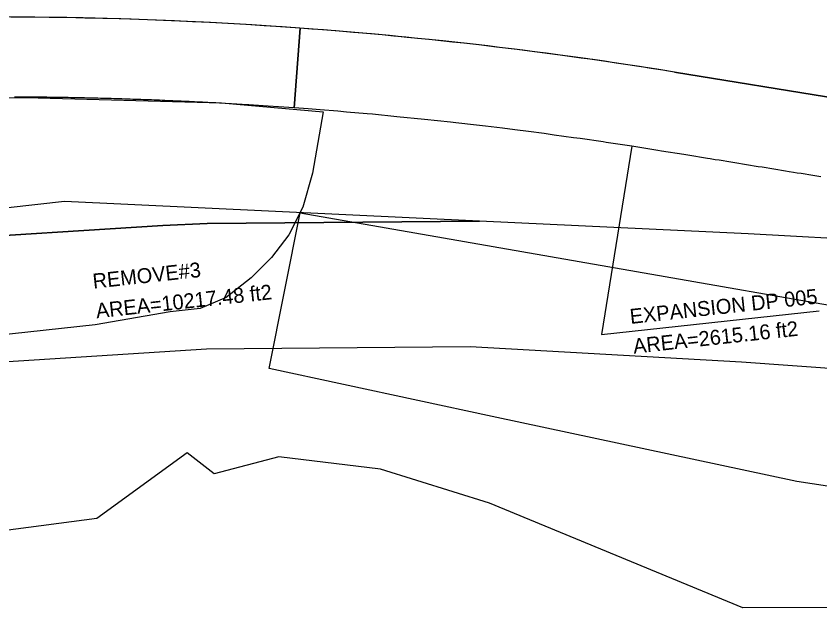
# Model space of a CAD drawing. Extents: x 1509538 to 1510847, y 401283 to 402022.
# Drawn here: x 1510184.5 to 1510335.3, y 401595.2 to 401706.3 of the extents above; entities that cross this region are included whole.
import ezdxf

# ---------------------------------------------------------------- set-up
doc = ezdxf.new("R2010")
doc.units = 0
for name, color, linetype in [('LAWE_P_T', 7, 'Continuous'), ('LDEFAULT_P', 7, 'Continuous'), ('Level 14', 7, 'Continuous'), ('Level 16', 7, 'Continuous'), ('Level 17', 7, 'Continuous'), ('Level 21', 7, 'Continuous'), ('Level 22', 7, 'Continuous'), ('Level 24', 7, 'Continuous'), ('Level 3', 7, 'Continuous'), ('Level 4', 7, 'Continuous')]:
    doc.layers.add(name, color=color, linetype=linetype)

msp = doc.modelspace()

# ---------------------------------------------------------------- linework, layer by layer
at = {"layer": 'LDEFAULT_P'}
msp.add_lwpolyline([(1510300.06, 401681.85), (1510294.35, 401646.54), (1510335.18, 401650.99)], dxfattribs=at)
at = {"layer": 'Level 14'}
msp.add_line((1510433.17, 401675.46), (1510308.05, 401695.77), dxfattribs=at)
msp.add_arc((1510179.87, 400906.1), 800, 80.78048, 96.2219, dxfattribs=at)
at = {"layer": 'Level 16'}
for p, q in [((1510184.72, 401691.09), (1510184.22, 401691.09)), ((1510185.23, 401691.08), (1510184.72, 401691.09)), ((1510185.73, 401691.08), (1510185.23, 401691.08)), ((1510186.24, 401691.08), (1510185.73, 401691.08)), ((1510186.74, 401691.07), (1510186.24, 401691.08)), ((1510187.25, 401691.07), (1510186.74, 401691.07)), ((1510187.75, 401691.06), (1510187.25, 401691.07)), ((1510188.25, 401691.06), (1510187.75, 401691.06)), ((1510188.76, 401691.05), (1510188.25, 401691.06)), ((1510189.26, 401691.04), (1510188.76, 401691.05)), ((1510189.77, 401691.04), (1510189.26, 401691.04)), ((1510190.27, 401691.03), (1510189.77, 401691.04)), ((1510190.77, 401691.02), (1510190.27, 401691.03)), ((1510191.28, 401691.02), (1510190.77, 401691.02)), ((1510191.78, 401691.01), (1510191.28, 401691.02)), ((1510192.29, 401691), (1510191.78, 401691.01)), ((1510192.79, 401690.99), (1510192.29, 401691)), ((1510193.3, 401690.99), (1510192.79, 401690.99)), ((1510193.8, 401690.98), (1510193.3, 401690.99)), ((1510194.3, 401690.97), (1510193.8, 401690.98)), ((1510194.81, 401690.96), (1510194.3, 401690.97)), ((1510195.31, 401690.95), (1510194.81, 401690.96)), ((1510195.82, 401690.94), (1510195.31, 401690.95)), ((1510196.32, 401690.93), (1510195.82, 401690.94)), ((1510196.82, 401690.92), (1510196.32, 401690.93)), ((1510197.33, 401690.91), (1510196.82, 401690.92)), ((1510197.83, 401690.9), (1510197.33, 401690.91)), ((1510198.34, 401690.88), (1510197.83, 401690.9)), ((1510198.84, 401690.87), (1510198.34, 401690.88)), ((1510199.34, 401690.86), (1510198.84, 401690.87)), ((1510199.85, 401690.85), (1510199.34, 401690.86)), ((1510200.35, 401690.83), (1510199.85, 401690.85)), ((1510200.86, 401690.82), (1510200.35, 401690.83)), ((1510201.36, 401690.81), (1510200.86, 401690.82)), ((1510201.86, 401690.79), (1510201.36, 401690.81)), ((1510202.37, 401690.78), (1510201.86, 401690.79)), ((1510202.87, 401690.76), (1510202.37, 401690.78)), ((1510203.38, 401690.75), (1510202.87, 401690.76)), ((1510203.88, 401690.73), (1510203.38, 401690.75)), ((1510204.38, 401690.72), (1510203.88, 401690.73)), ((1510204.89, 401690.7), (1510204.38, 401690.72)), ((1510205.39, 401690.69), (1510204.89, 401690.7)), ((1510205.9, 401690.67), (1510205.39, 401690.69)), ((1510206.4, 401690.65), (1510205.9, 401690.67)), ((1510206.9, 401690.64), (1510206.4, 401690.65)), ((1510207.41, 401690.62), (1510206.9, 401690.64)), ((1510207.91, 401690.6), (1510207.41, 401690.62)), ((1510208.42, 401690.58), (1510207.91, 401690.6)), ((1510208.92, 401690.56), (1510208.42, 401690.58)), ((1510209.42, 401690.54), (1510208.92, 401690.56)), ((1510209.93, 401690.53), (1510209.42, 401690.54)), ((1510210.43, 401690.51), (1510209.93, 401690.53)), ((1510210.93, 401690.49), (1510210.43, 401690.51)), ((1510211.44, 401690.47), (1510210.93, 401690.49)), ((1510211.94, 401690.45), (1510211.44, 401690.47)), ((1510212.45, 401690.42), (1510211.94, 401690.45)), ((1510212.95, 401690.4), (1510212.45, 401690.42)), ((1510213.45, 401690.38), (1510212.95, 401690.4)), ((1510213.96, 401690.36), (1510213.45, 401690.38)), ((1510214.46, 401690.34), (1510213.96, 401690.36)), ((1510214.96, 401690.32), (1510214.46, 401690.34)), ((1510215.47, 401690.29), (1510214.96, 401690.32)), ((1510215.97, 401690.27), (1510215.47, 401690.29)), ((1510216.48, 401690.25), (1510215.97, 401690.27)), ((1510216.98, 401690.22), (1510216.48, 401690.25)), ((1510217.48, 401690.2), (1510216.98, 401690.22)), ((1510217.99, 401690.17), (1510217.48, 401690.2)), ((1510218.49, 401690.15), (1510217.99, 401690.17)), ((1510218.99, 401690.13), (1510218.49, 401690.15)), ((1510219.5, 401690.1), (1510218.99, 401690.13)), ((1510220, 401690.08), (1510219.5, 401690.1)), ((1510220.5, 401690.05), (1510220, 401690.08)), ((1510221.01, 401690.02), (1510220.5, 401690.05)), ((1510221.51, 401690), (1510221.01, 401690.02)), ((1510222.02, 401689.97), (1510221.51, 401690)), ((1510222.66, 401689.93), (1510222.02, 401689.97)), ((1510224.95, 401689.81), (1510222.66, 401689.93)), ((1510226.91, 401689.69), (1510224.95, 401689.81)), ((1510228.21, 401689.61), (1510226.91, 401689.69)), ((1510231.81, 401689.38), (1510228.21, 401689.61)), ((1510233.77, 401689.25), (1510231.81, 401689.38)), ((1510236.7, 401689.04), (1510233.77, 401689.25))]:
    msp.add_line(p, q, dxfattribs=at)
msp.add_lwpolyline([(1510237.79, 401704), (1510236.7, 401689.04)], dxfattribs=at)
msp.add_arc((1510179.87, 400906.1), 800, 85.84827, 96.2219, dxfattribs=at)
at = {"layer": 'Level 17'}
for p, q in [((1510236.7, 401689.04), (1510237.79, 401704)), ((1510308.05, 401695.77), (1510410.94, 401679.07)), ((1510236.7, 401689.04), (1510236.7, 401689.04)), ((1510239.32, 401688.85), (1510236.7, 401689.04)), ((1510241.6, 401688.67), (1510239.32, 401688.85)), ((1510244.87, 401688.41), (1510241.6, 401688.67)), ((1510246.49, 401688.27), (1510244.87, 401688.41)), ((1510250.42, 401687.92), (1510246.49, 401688.27)), ((1510251.37, 401687.84), (1510250.42, 401687.92)), ((1510255.96, 401687.4), (1510251.37, 401687.84)), ((1510261.14, 401686.88), (1510255.96, 401687.4)), ((1510266.02, 401686.36), (1510261.14, 401686.88)), ((1510267.04, 401686.25), (1510266.02, 401686.36)), ((1510270.89, 401685.81), (1510267.04, 401686.25)), ((1510272.57, 401685.61), (1510270.89, 401685.81)), ((1510275.76, 401685.22), (1510272.57, 401685.61)), ((1510278.09, 401684.93), (1510275.76, 401685.22)), ((1510280.63, 401684.61), (1510278.09, 401684.93)), ((1510283.61, 401684.22), (1510280.63, 401684.61)), ((1510285.5, 401683.96), (1510283.61, 401684.22)), ((1510289.13, 401683.46), (1510285.5, 401683.96)), ((1510290.35, 401683.29), (1510289.13, 401683.46)), ((1510294.64, 401682.67), (1510290.35, 401683.29)), ((1510295.21, 401682.58), (1510294.64, 401682.67)), ((1510300.06, 401681.85), (1510295.21, 401682.58)), ((1510304.91, 401681.08), (1510300.06, 401681.85)), ((1510305.64, 401680.96), (1510304.91, 401681.08)), ((1510309.83, 401680.28), (1510305.64, 401680.96)), ((1510310.56, 401680.16), (1510309.83, 401680.28)), ((1510311.29, 401680.04), (1510310.56, 401680.16)), ((1510312.03, 401679.92), (1510311.29, 401680.04)), ((1510312.76, 401679.8), (1510312.03, 401679.92)), ((1510313.49, 401679.69), (1510312.76, 401679.8)), ((1510314.23, 401679.57), (1510313.49, 401679.69)), ((1510314.76, 401679.48), (1510314.23, 401679.57)), ((1510315.69, 401679.33), (1510314.76, 401679.48)), ((1510316.42, 401679.21), (1510315.69, 401679.33)), ((1510317.16, 401679.09), (1510316.42, 401679.21)), ((1510317.89, 401678.97), (1510317.16, 401679.09)), ((1510318.62, 401678.85), (1510317.89, 401678.97)), ((1510319.36, 401678.73), (1510318.62, 401678.85)), ((1510320.09, 401678.61), (1510319.36, 401678.73)), ((1510320.82, 401678.5), (1510320.09, 401678.61)), ((1510321.56, 401678.38), (1510320.82, 401678.5)), ((1510322.29, 401678.26), (1510321.56, 401678.38)), ((1510323.02, 401678.14), (1510322.29, 401678.26)), ((1510323.75, 401678.02), (1510323.02, 401678.14)), ((1510324.49, 401677.9), (1510323.75, 401678.02)), ((1510325.22, 401677.78), (1510324.49, 401677.9)), ((1510325.95, 401677.66), (1510325.22, 401677.78)), ((1510326.69, 401677.54), (1510325.95, 401677.66)), ((1510327.42, 401677.43), (1510326.69, 401677.54)), ((1510328.15, 401677.31), (1510327.42, 401677.43)), ((1510328.89, 401677.19), (1510328.15, 401677.31)), ((1510329.57, 401677.08), (1510328.89, 401677.19)), ((1510330.35, 401676.95), (1510329.57, 401677.08)), ((1510331.08, 401676.83), (1510330.35, 401676.95)), ((1510331.82, 401676.71), (1510331.08, 401676.83)), ((1510332.55, 401676.59), (1510331.82, 401676.71)), ((1510333.28, 401676.47), (1510332.55, 401676.59)), ((1510334.02, 401676.35), (1510333.28, 401676.47)), ((1510334.75, 401676.24), (1510334.02, 401676.35)), ((1510335.48, 401676.12), (1510334.75, 401676.24))]:
    msp.add_line(p, q, dxfattribs=at)
msp.add_arc((1510179.87, 400906.1), 800, 80.78048, 85.84827, dxfattribs=at)
at = {"layer": 'Level 21'}
msp.add_lwpolyline([(1510242.15, 401688.33), (1510240.12, 401676.82), (1510238.33, 401670.41), (1510235.71, 401665.22), (1510232.46, 401660.96), (1510228.6, 401657.18), (1510223.92, 401653.49), (1510219.07, 401651.42), (1510213.42, 401650.8), (1510199.34, 401648.36), (1510124.09, 401640.16), (1510070.35, 401634.35), (1510069.7, 401640.31), (1510152.54, 401649.19), (1510122.02, 401663.28), (1510130.83, 401671.08), (1510129.8, 401686.5), (1510116.98, 401685.56), (1510115.9, 401688.49), (1510149.69, 401690.52), (1510186.34, 401691), (1510223.03, 401690)], close=True, dxfattribs=at)
at = {"layer": 'Level 22'}
msp.add_lwpolyline([(1510163.27, 401729.57), (1510193.23, 401729.63), (1510240, 401727.48), (1510240.05, 401735.46), (1510249.26, 401738.71), (1510293.27, 401739.88), (1510404.63, 401716.65), (1510416.62, 401714.21), (1510414.07, 401699.18), (1510406.28, 401635.45), (1510397.88, 401621.86), (1510377.81, 401611.86), (1510331.03, 401618.95), (1510273.83, 401631.15), (1510231.99, 401640.14), (1510237.83, 401669.36), (1510405.63, 401640.09), (1510412.68, 401699.55), (1510362.56, 401707.65), (1510292.37, 401718.82), (1510261.04, 401722.38), (1510232.33, 401724.97), (1510197.61, 401726.48), (1510164.02, 401726.59)], dxfattribs=at)
at = {"layer": 'Level 24'}
msp.add_lwpolyline([(1510422.96, 401609.85), (1510373.65, 401595.47), (1510320.84, 401595.24), (1510273.34, 401614.89), (1510252.89, 401621.29), (1510233.84, 401623.61), (1510221.68, 401620.37), (1510216.62, 401624.36), (1510199.65, 401612.04), (1510126.95, 401602.48), (1510061.48, 401610.5), (1510058.01, 401613.13), (1509981.47, 401601.19), (1509974.39, 401646.63)], dxfattribs=at)
at = {"layer": 'Level 3'}
msp.add_lwpolyline([(1510335.48, 401676.12), (1510334.75, 401676.24), (1510334.02, 401676.35), (1510333.28, 401676.47), (1510332.55, 401676.59), (1510331.82, 401676.71), (1510331.08, 401676.83), (1510330.35, 401676.95), (1510329.57, 401677.08), (1510328.89, 401677.19), (1510328.15, 401677.31), (1510327.42, 401677.43), (1510326.69, 401677.54), (1510325.95, 401677.66), (1510325.22, 401677.78), (1510324.49, 401677.9), (1510323.75, 401678.02), (1510323.02, 401678.14), (1510322.29, 401678.26), (1510321.56, 401678.38), (1510320.82, 401678.5), (1510320.09, 401678.61), (1510319.36, 401678.73), (1510318.62, 401678.85), (1510317.89, 401678.97), (1510317.16, 401679.09), (1510316.42, 401679.21), (1510315.69, 401679.33), (1510314.76, 401679.48), (1510314.23, 401679.57), (1510313.49, 401679.69), (1510312.76, 401679.8), (1510312.03, 401679.92), (1510311.29, 401680.04), (1510310.56, 401680.16), (1510309.83, 401680.28), (1510305.64, 401680.96), (1510304.91, 401681.08), (1510300.06, 401681.85), (1510295.21, 401682.58), (1510294.64, 401682.67), (1510290.35, 401683.29), (1510289.13, 401683.46), (1510285.5, 401683.96), (1510283.61, 401684.22), (1510280.63, 401684.61), (1510278.09, 401684.93), (1510275.76, 401685.22), (1510272.57, 401685.61), (1510270.89, 401685.81), (1510267.04, 401686.25), (1510266.02, 401686.36), (1510261.14, 401686.88), (1510255.96, 401687.4), (1510251.37, 401687.84), (1510250.42, 401687.92), (1510246.49, 401688.27), (1510244.87, 401688.41), (1510241.6, 401688.67), (1510239.32, 401688.85), (1510236.7, 401689.04), (1510233.77, 401689.25), (1510231.81, 401689.38), (1510228.21, 401689.61), (1510226.91, 401689.69), (1510224.95, 401689.81), (1510222.66, 401689.93), (1510222.02, 401689.97), (1510221.51, 401690), (1510221.01, 401690.02), (1510220.5, 401690.05), (1510220, 401690.08), (1510219.5, 401690.1), (1510218.99, 401690.13), (1510218.49, 401690.15), (1510217.99, 401690.17), (1510217.48, 401690.2), (1510216.98, 401690.22), (1510216.48, 401690.25), (1510215.97, 401690.27), (1510215.47, 401690.29), (1510214.96, 401690.32), (1510214.46, 401690.34), (1510213.96, 401690.36), (1510213.45, 401690.38), (1510212.95, 401690.4), (1510212.45, 401690.42), (1510211.94, 401690.45), (1510211.44, 401690.47), (1510210.93, 401690.49), (1510210.43, 401690.51), (1510209.93, 401690.53), (1510209.42, 401690.54), (1510208.92, 401690.56), (1510208.42, 401690.58), (1510207.91, 401690.6), (1510207.41, 401690.62), (1510206.9, 401690.64), (1510206.4, 401690.65), (1510205.9, 401690.67), (1510205.39, 401690.69), (1510204.89, 401690.7), (1510204.38, 401690.72), (1510203.88, 401690.73), (1510203.38, 401690.75), (1510202.87, 401690.76), (1510202.37, 401690.78), (1510201.86, 401690.79), (1510201.36, 401690.81), (1510200.86, 401690.82), (1510200.35, 401690.83), (1510199.85, 401690.85), (1510199.34, 401690.86), (1510198.84, 401690.87), (1510198.34, 401690.88), (1510197.83, 401690.9), (1510197.33, 401690.91), (1510196.82, 401690.92), (1510196.32, 401690.93), (1510195.82, 401690.94), (1510195.31, 401690.95), (1510194.81, 401690.96), (1510194.3, 401690.97), (1510193.8, 401690.98), (1510193.3, 401690.99), (1510192.79, 401690.99), (1510192.29, 401691), (1510191.78, 401691.01), (1510191.28, 401691.02), (1510190.77, 401691.02), (1510190.27, 401691.03), (1510189.77, 401691.04), (1510189.26, 401691.04), (1510188.76, 401691.05), (1510188.25, 401691.06), (1510187.75, 401691.06), (1510187.25, 401691.07), (1510186.74, 401691.07), (1510186.24, 401691.08), (1510185.73, 401691.08), (1510185.23, 401691.08), (1510184.72, 401691.09), (1510184.22, 401691.09)], dxfattribs=at)
at = {"layer": 'Level 4'}
msp.add_line((1510220.39, 401667.36), (1510271.44, 401667.79), dxfattribs=at)
for points in [[(1510271.44, 401667.79), (1510193.59, 401671.47), (1510117.88, 401663), (1510068.52, 401654.76)], [(1510271.44, 401667.79), (1510193.59, 401671.47), (1510117.88, 401663), (1510068.52, 401654.76)], [(1510271.44, 401667.79), (1510193.59, 401671.47), (1510117.88, 401663)], [(1510420.35, 401661.34), (1510371.76, 401662.64), (1510321.9, 401665.44), (1510271.44, 401667.79), (1510220.39, 401667.36), (1510212.05, 401667), (1510168.51, 401664.21), (1510117.95, 401657.12), (1510069.7, 401647.38)], [(1510069.7, 401647.38), (1510117.95, 401657.12), (1510168.51, 401664.21), (1510212.05, 401667), (1510220.39, 401667.36), (1510271.44, 401667.79)], [(1510168.51, 401664.21), (1510212.05, 401667), (1510220.39, 401667.36)], [(1510069.7, 401647.38), (1510070.82, 401637.95), (1510072.41, 401628.04), (1510122.3, 401634.81), (1510170.19, 401640.65), (1510220.23, 401643.86), (1510269.72, 401644.29), (1510320.63, 401641.42), (1510370.24, 401637.87), (1510421.73, 401637.03), (1510472.3, 401638.25), (1510523.24, 401640.81), (1510571.7, 401643.53), (1510601.13, 401645.2)]]:
    msp.add_lwpolyline(points, dxfattribs=at)

# ---------------------------------------------------------------- texts
at = {"layer": 'LAWE_P_T'}
for s, p in [('REMOVE#3', (1510199.04, 401655.13)), ('AREA=10217.48 ft2', (1510199.64, 401649.57))]:
    msp.add_text(s, height=2.8, rotation=6.2219, dxfattribs=at).set_placement(p)
at = {"layer": 'LDEFAULT_P'}
for s, p in [('EXPANSION DP 005', (1510299.82, 401648.51)), ('AREA=2615.16 ft2', (1510300.43, 401642.94))]:
    msp.add_text(s, height=2.8, rotation=6.2219, dxfattribs=at).set_placement(p)

doc.saveas('drawing.dxf')
